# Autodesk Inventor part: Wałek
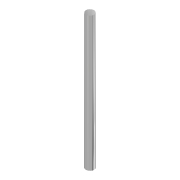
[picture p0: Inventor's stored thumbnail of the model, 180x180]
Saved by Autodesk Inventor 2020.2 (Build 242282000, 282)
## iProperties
Created: 2005-10
Part Number: Wałek
Document SubType Name: Modeling
Designer: F.Stasiak
Density: 1 g/cm^3
Material: Ogólny
Appearance: Chrom — polerowany
Manager: www.cadconsulting.pl
Company: Fabian Stasiak CAD Consulting
Author: F.Stasiak
Subject: Zbiór ćwiczeń. Autodesk Inventor 2020. Kurs podstawowy
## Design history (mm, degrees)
sketch "Szkic1"
  geometry: C1 r 3 at (0, 0); 1 further point
  constraints: 1 centre point, 1 coincident
  dimensions: "d0" = 6 diameter of C1
extrude "Wyciągnięcie proste1" new body sketch "Szkic1" stored distance "d1" = 100; taper "d2" = 0 deg
node "Bryła1"
node "Korpusy bryłowe"
node "Korpusy powierzchniowe"
